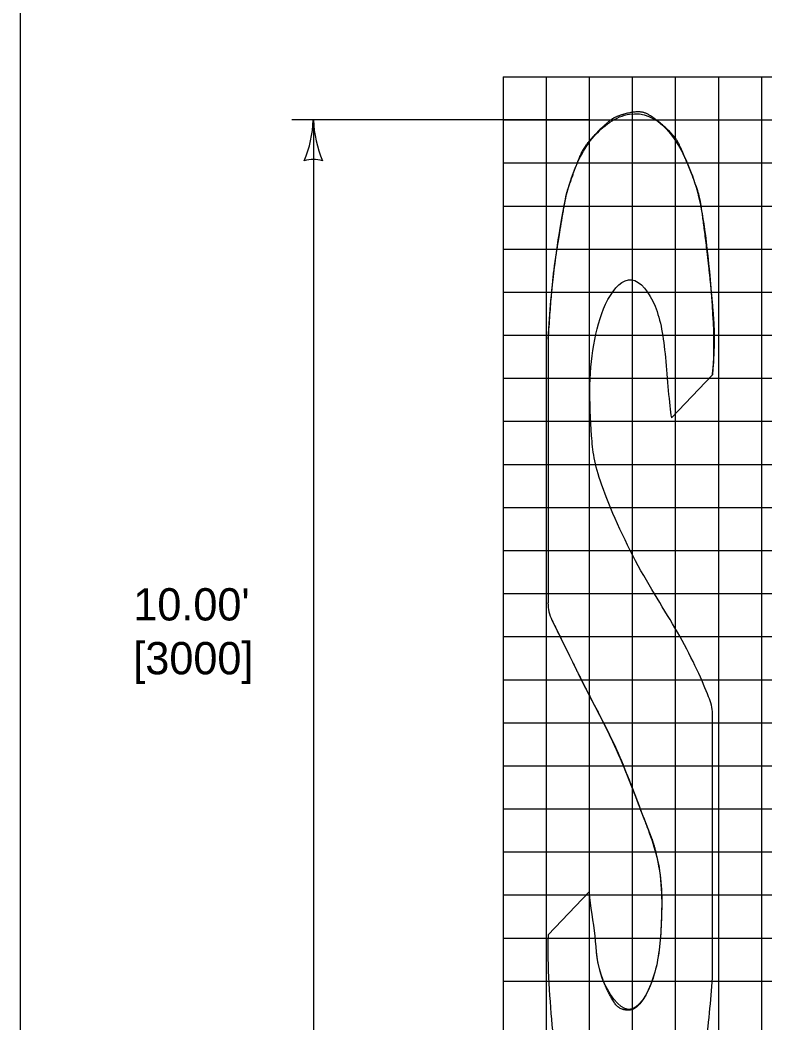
# Model space of a CAD drawing. Extents: x 49991.4 to 50021, y 49987.6 to 50011.4.
# Drawn here: x 50000.336 to 50001.719, y 50003.979 to 50005.842 of the extents above; entities that cross this region are included whole.
import ezdxf

# ---------------------------------------------------------------- set-up
doc = ezdxf.new("R2010")
doc.units = 0
for name, color, linetype in [('Level 1', 7, 'Continuous'), ('Level 2', 7, 'Continuous'), ('Level 3', 7, 'Continuous'), ('Level 9', 7, 'Continuous')]:
    doc.layers.add(name, color=color, linetype=linetype)

msp = doc.modelspace()

# ---------------------------------------------------------------- linework, layer by layer
at = {"layer": 'Level 1'}
for p, q in [((50001.3162, 50005.2492), (50001.3162, 50004.759)), ((50001.3162, 50005.2492), (50001.3162, 50004.759)), ((50001.3162, 50005.2492), (50001.3162, 50004.759)), ((50001.6216, 50005.1826), (50001.5453, 50005.1026)), ((50001.5453, 50005.1026), (50001.6216, 50005.1826)), ((50001.5453, 50005.1026), (50001.6216, 50005.1826)), ((50001.6216, 50004.0622), (50001.6216, 50004.5528)), ((50001.6216, 50004.0622), (50001.6216, 50004.5528)), ((50001.6216, 50004.0622), (50001.6216, 50004.5528)), ((50001.3162, 50004.1422), (50001.3926, 50004.2223)), ((50001.3926, 50004.2223), (50001.3162, 50004.1422)), ((50001.3926, 50004.2223), (50001.3162, 50004.1422))]:
    msp.add_line(p, q, dxfattribs=at)
msp.add_lwpolyline([(50008.6146, 50011.2628), (50000.3356, 50011.2628), (50000.3356, 50000.0624), (50008.6146, 50000.0624)], close=True, dxfattribs=at)
for centre, major_axis, start_param, end_param in [((50001.3779, 50004.759), (0, -0.0678), 4.712389, 5.204685), ((50001.3779, 50004.759), (0, -0.0678), 4.712389, 5.204685), ((50001.3779, 50004.759), (0, -0.0678), 4.712389, 5.204685), ((50001.5599, 50004.5528), (0, 0.0678), 4.712389, 5.199618), ((50001.5599, 50004.5528), (0, 0.0678), 4.712404, 5.199618), ((50001.5599, 50004.5528), (0, 0.0678), 4.712389, 5.199618)]:
    msp.add_ellipse(centre, major_axis=major_axis, ratio=0.910607, start_param=start_param, end_param=end_param, dxfattribs=at)
for points, degree in [([(50001.3162, 50005.2492), (50001.3229, 50005.3541), (50001.3424, 50005.4812), (50001.3541, 50005.5391), (50001.3918, 50005.6275), (50001.4687, 50005.6811), (50001.54, 50005.6504), (50001.5888, 50005.552), (50001.6108, 50005.4541), (50001.628, 50005.2409), (50001.6216, 50005.1826)], 3), ([(50001.4573, 50005.6669), (50001.442, 50005.6625), (50001.4268, 50005.6519), (50001.4141, 50005.6396)], 2), ([(50001.4573, 50005.6669), (50001.442, 50005.6625), (50001.4268, 50005.6519), (50001.4141, 50005.6396)], 2), ([(50001.5302, 50005.6459), (50001.5107, 50005.663), (50001.484, 50005.6745), (50001.4573, 50005.6669)], 2), ([(50001.5302, 50005.6459), (50001.5107, 50005.663), (50001.484, 50005.6745), (50001.4573, 50005.6669)], 2), ([(50001.5743, 50005.5773), (50001.5644, 50005.6013), (50001.5516, 50005.627), (50001.5302, 50005.6459)], 2), ([(50001.5743, 50005.5773), (50001.5644, 50005.6013), (50001.5516, 50005.627), (50001.5302, 50005.6459)], 2), ([(50001.4141, 50005.6396), (50001.3851, 50005.6116), (50001.3696, 50005.5755), (50001.3602, 50005.5491)], 2), ([(50001.4141, 50005.6396), (50001.3851, 50005.6116), (50001.3696, 50005.5755), (50001.3602, 50005.5491)], 2), ([(50001.6113, 50005.4153), (50001.6024, 50005.4914), (50001.5935, 50005.5313), (50001.5743, 50005.5773)], 2), ([(50001.6114, 50005.4153), (50001.6024, 50005.4914), (50001.5935, 50005.5313), (50001.5743, 50005.5773)], 2), ([(50001.3602, 50005.5491), (50001.3507, 50005.5226), (50001.3474, 50005.506), (50001.3422, 50005.4755)], 2), ([(50001.3602, 50005.5491), (50001.3507, 50005.5226), (50001.3474, 50005.506), (50001.3422, 50005.4755)], 2), ([(50001.3422, 50005.4755), (50001.3346, 50005.4301), (50001.3229, 50005.3541), (50001.3162, 50005.2492)], 2), ([(50001.3422, 50005.4755), (50001.3346, 50005.4301), (50001.3229, 50005.3541), (50001.3162, 50005.2492)], 2), ([(50001.6216, 50005.1826), (50001.628, 50005.2409), (50001.6197, 50005.344), (50001.6114, 50005.4153)], 2), ([(50001.6216, 50005.1826), (50001.628, 50005.2409), (50001.6197, 50005.344), (50001.6114, 50005.4153)], 2), ([(50001.6144, 50004.5846), (50001.6044, 50004.6112), (50001.5645, 50004.6989), (50001.4837, 50004.8181), (50001.4041, 50004.9956), (50001.3969, 50005.0641), (50001.3917, 50005.1669), (50001.4012, 50005.2489), (50001.423, 50005.3266), (50001.4715, 50005.3786), (50001.5209, 50005.3147), (50001.5354, 50005.2233), (50001.541, 50005.1279), (50001.5453, 50005.1026)], 3), ([(50001.6144, 50004.5846), (50001.6044, 50004.6112), (50001.5645, 50004.6989), (50001.4837, 50004.8181), (50001.4041, 50004.9956), (50001.3969, 50005.0641), (50001.3917, 50005.1669), (50001.4012, 50005.2489), (50001.423, 50005.3266), (50001.4715, 50005.3786), (50001.5209, 50005.3147), (50001.5354, 50005.2233), (50001.541, 50005.1279), (50001.5453, 50005.1026)], 3), ([(50001.6144, 50004.5846), (50001.6044, 50004.6112), (50001.5645, 50004.6989), (50001.4837, 50004.8181), (50001.4041, 50004.9956), (50001.3969, 50005.0641), (50001.3917, 50005.1669), (50001.4012, 50005.2489), (50001.423, 50005.3266), (50001.4715, 50005.3786), (50001.5209, 50005.3147), (50001.5354, 50005.2233), (50001.541, 50005.1279), (50001.5453, 50005.1026)], 3), ([(50001.3235, 50004.727), (50001.3664, 50004.6399), (50001.3896, 50004.5912), (50001.4448, 50004.4907), (50001.4906, 50004.3664), (50001.5292, 50004.2707), (50001.5276, 50004.1542), (50001.5179, 50004.06), (50001.4676, 50003.9746), (50001.4072, 50004.064), (50001.4059, 50004.1385), (50001.3955, 50004.1946), (50001.3926, 50004.2223)], 3), ([(50001.3235, 50004.727), (50001.3664, 50004.6399), (50001.3896, 50004.5912), (50001.4229, 50004.5305), (50001.4393, 50004.4948)], 3), ([(50001.3235, 50004.727), (50001.3664, 50004.6399), (50001.3775, 50004.6168), (50001.3908, 50004.5909)], 2), ([(50001.3908, 50004.5909), (50001.4055, 50004.5623), (50001.4448, 50004.4907), (50001.4786, 50004.399), (50001.4941, 50004.3587)], 3), ([(50001.4393, 50004.4948), (50001.4598, 50004.45), (50001.4906, 50004.3664), (50001.5292, 50004.2707), (50001.5276, 50004.1542), (50001.5179, 50004.06), (50001.4676, 50003.9746), (50001.4072, 50004.064), (50001.4059, 50004.1385), (50001.3955, 50004.1946), (50001.3926, 50004.2223)], 3), ([(50001.4941, 50004.3587), (50001.5041, 50004.3329), (50001.5128, 50004.3115), (50001.5183, 50004.2869)], 2), ([(50001.5183, 50004.2869), (50001.5288, 50004.2401), (50001.5276, 50004.1542), (50001.5179, 50004.06), (50001.4851, 50004.0043), (50001.4689, 50004.0026)], 3), ([(50001.4186, 50004.058), (50001.4068, 50004.0874), (50001.4059, 50004.1385), (50001.3955, 50004.1946), (50001.3926, 50004.2223)], 3), ([(50001.3162, 50004.1422), (50001.3145, 50004.0858), (50001.3242, 50003.9507), (50001.3402, 50003.8315), (50001.391, 50003.6994), (50001.469, 50003.6432), (50001.5595, 50003.7087), (50001.5918, 50003.8059), (50001.6089, 50003.9265), (50001.619, 50004.021), (50001.6216, 50004.0622)], 3), ([(50001.3162, 50004.1422), (50001.3145, 50004.0858), (50001.3242, 50003.9507), (50001.3402, 50003.8315), (50001.391, 50003.6994), (50001.469, 50003.6432), (50001.5595, 50003.7087), (50001.5918, 50003.8059), (50001.6089, 50003.9265), (50001.619, 50004.021), (50001.6216, 50004.0622)], 3), ([(50001.3162, 50004.1422), (50001.3145, 50004.0858), (50001.3242, 50003.9507), (50001.3402, 50003.8315), (50001.391, 50003.6994), (50001.469, 50003.6432), (50001.5595, 50003.7087), (50001.5918, 50003.8059), (50001.6089, 50003.9265), (50001.619, 50004.021), (50001.6216, 50004.0622)], 3), ([(50001.4689, 50004.0026), (50001.45, 50004.0006), (50001.4295, 50004.031), (50001.4186, 50004.058)], 2)]:
    msp.add_open_spline(points, degree=degree, dxfattribs=at)
at = {"layer": 'Level 3'}
for p, q in [((50001.3932, 50005.6563), (50000.8404, 50005.6563)), ((50000.8804, 50005.6563), (50000.8804, 50003.6563))]:
    msp.add_line(p, q, dxfattribs=at)
for centre, radius, start, end in [((50000.6582, 50005.6655), 0.2223, 337.456, 357.6395), ((50001.1131, 50005.6678), 0.233, 182.8273, 202.0772), ((50000.8804, 50005.5281), 0.0548, 72.1388, 107.8612)]:
    msp.add_arc(centre, radius, start, end, dxfattribs=at)
at = {"layer": 'Level 9'}
for p, q in [((50001.2327, 50005.7363), (50003.7127, 50005.7363)), ((50001.2327, 50005.7363), (50001.2327, 50003.5763)), ((50001.3127, 50005.7363), (50001.3127, 50003.5763)), ((50001.3927, 50005.7363), (50001.3927, 50003.5763)), ((50001.4727, 50005.7363), (50001.4727, 50003.5763)), ((50001.5527, 50005.7363), (50001.5527, 50003.5763)), ((50001.6327, 50005.7363), (50001.6327, 50003.5763)), ((50001.7127, 50005.7363), (50001.7127, 50003.5763)), ((50001.2327, 50005.6563), (50003.7127, 50005.6563)), ((50001.2327, 50005.5763), (50003.7127, 50005.5763)), ((50001.2327, 50005.4963), (50003.7127, 50005.4963)), ((50001.2327, 50005.4163), (50003.7127, 50005.4163)), ((50001.2327, 50005.3363), (50003.7127, 50005.3363)), ((50001.2327, 50005.2563), (50003.7127, 50005.2563)), ((50001.2327, 50005.1763), (50003.7127, 50005.1763)), ((50001.2327, 50005.0963), (50003.7127, 50005.0963)), ((50001.2327, 50005.0163), (50003.7127, 50005.0163)), ((50001.2327, 50004.9363), (50003.7127, 50004.9363)), ((50001.2327, 50004.8563), (50003.7127, 50004.8563)), ((50001.2327, 50004.7763), (50003.7127, 50004.7763)), ((50001.2327, 50004.6963), (50003.7127, 50004.6963)), ((50001.2327, 50004.6163), (50003.7127, 50004.6163)), ((50001.2327, 50004.5363), (50003.7127, 50004.5363)), ((50001.2327, 50004.4563), (50003.7127, 50004.4563)), ((50001.2327, 50004.3763), (50003.7127, 50004.3763)), ((50001.2327, 50004.2963), (50003.7127, 50004.2963)), ((50001.2327, 50004.2163), (50003.7127, 50004.2163)), ((50001.2327, 50004.1363), (50003.7127, 50004.1363)), ((50001.2327, 50004.0563), (50003.7127, 50004.0563))]:
    msp.add_line(p, q, dxfattribs=at)

# ---------------------------------------------------------------- texts
at = {"layer": 'Level 2'}
for s, p in [("10.00'", (50000.546, 50004.7263)), ('[3000]', (50000.546, 50004.6263))]:
    msp.add_text(s, height=0.06, dxfattribs=at).set_placement(p)

doc.saveas('drawing.dxf')
